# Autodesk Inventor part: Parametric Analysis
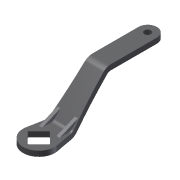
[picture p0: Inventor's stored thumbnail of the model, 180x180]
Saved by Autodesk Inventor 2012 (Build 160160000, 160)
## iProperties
Created: 2008-02
Part Number: Parametric Analysis
Material: Domex 355_SM
Document SubType Name: Sheet Metal
Designer: maxfiep
Density: 7.8 g/cm^3
Mass: 6351 g
Surface Area: 1123.64 cm^2
Volume: 814.231 cm^3
Sheet Metal Rule: Default
RuleStatus: InUse
Author: maxfiep
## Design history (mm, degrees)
node "Contour Flange1"
  sketch "Sketch1"
    geometry: L1 (0, 0)-(80, 0); L2 (80, 0)-(220, 140); L3 (220, 140)-(411, 140); L4 (0, 168)-(0, -28) reference; L5 (-82.2, 0)-(493.2, 0) reference; 1 further point
    constraints: 6 end point, 1 parallel
    dimensions: "d0" = 140 distance between parallel lines of L3 L1; "d2" = 135 deg angle of L3 L2; "d3" = 80 distance of L1.start L1.end
node "Face1"
  sketch "Sketch2"
    geometry: L1 (0, 71.716)-(0, 0) reference; L2 (120, 71.716)-(0, 71.716) reference; L3 (0, 71.716)-(0, 0) reference; L4 (120, 0)-(0, 0) reference; L5 (120, 71.716)-(120, 0) reference; A1 r 60 centre (60, 0) between (0, 0) and (120, 0); 1 further point
    constraints: 2 point on circle, 2 tangent, 1 centre point
sketch "Sketch3"
  geometry: L1 (0, 0)-(0, -71.716) reference; L2 (120, 0)-(120, -71.716) reference; L3 (0, -71.716)-(120, -71.716); L4 (60, -71.716)-(60, 0); L5 (17.574, -71.716)-(60, -29.289); L6 (60, -29.289)-(102.426, -71.716); L7 (102.426, -71.716)-(60, -114.142); L8 (60, -114.142)-(17.574, -71.716); 2 further points
  constraints: 12 end point, 2 coincident, 2 perpendicular, 1 horizontal alignment, 1 midpoint, 1 point on line, 11 other
  dimensions: "d19" = 60 distance of L7.end L5.start
cut "Cut1" sketch "Sketch3" dims "d22" = 20 (= Thickness), "d23" = 0
sketch "Sketch4"
  geometry: L1 (0, 0)-(120, 0) reference; L2 (-1489.511, -411)-(1609.511, -411) reference; L3 (0, -174.431)-(120, -174.431) reference; L4 (25, -174.431)-(25, 0); L5 (0, -174.431)-(0, 0) reference; L6 (60, -174.431)-(60, -411); L7 (60, -471)-(60, -923.049); L8 (25, 0)-(-30.859, 0); L9 (-30.859, 0)-(-30.859, -503.072); L10 (-30.859, -503.072)-(60, -503.072); L11 (150.859, -503.072)-(60, -503.072); L12 (150.859, 0)-(150.859, -503.072); L13 (95, -174.431)-(95, 0); L14 (95, 0)-(150.859, 0); A1 r 60 centre (60, -411) between (0, -411) and (120, -411) reference; A2 r 60 centre (60, -411) between (1.325, -398.459) and (60, -471); A3 r 1071.794 centre (-1046.794, -174.431) between (1.325, -398.459) and (25, -174.431); A4 r 60 centre (60, -411) between (60, -471) and (118.675, -398.459); A5 r 1071.794 centre (1166.794, -174.431) between (95, -174.431) and (118.675, -398.459)
  constraints: 20 end point, 9 point on circle, 6 symmetric about line, 4 centre point, 4 perpendicular, 3 point on line, 2 coincident, 2 midpoint, 2 tangent, 1 concentric, 1 horizontal, 1 parallel, 2 other
  dimensions: "d24" = 25 distance between parallel lines of L4 L5
cut "Cut2" sketch "Sketch4" dims "d25" = 20 (= Thickness), "d26" = 0
sketch "Sketch5"
  geometry: L1 (70, -174.431)-(70, 0) reference; L2 (0, 0)-(70, 0) reference; L3 (0, 0)-(0, -174.431) reference; L4 (0, -174.431)-(70, -174.431) reference; A1 r 35 centre (35, 0) between (70, 0) and (0, 0); 1 further point
  constraints: 2 point on circle, 2 tangent, 1 centre point, 1 coincident
  node "Projected Loop2"
node "Face2"
hole "Hole1" sketch "Sketch5" diameter "d32" = 25; stored, may be unused: countersink angle "d36" = 90 deg, drill point angle "d38" = 118 deg; dims "d33" = 6, "d34" = 4, "d35" = 2, "d37" = 20 (= Thickness)
fillet "Fillet1" dims "d39" = 1
feature "Corner Round1" dims "d40" = 3
workplane "Work Plane1"
workplane "Work Plane2"
sketch "Sketch7"
  geometry: L1 (92.998, 108)-(92.998, 48); L2 (27.002, 108)-(27.002, 48); L3 (27.002, 78)-(92.998, 78); 6 further points; 1 other entity
  constraints: 6 end point, 3 midpoint, 2 vertical, 1 horizontal, 1 parallel, 1 vertical alignment, 4 other
  dimensions: "d77" = 78 distance of point (60, 0) point (60, 78); "d78" = 60 distance of L1.start L1.end
feature "Rib1" sketch "Sketch7" dims "d79" = 12, "d80" = 1, "d81" = 0
body "Solid1"
face "Plate1" dims "d4" = 20 (= BendReliefWidth), "d5" = 10 (= BendReliefDepth), "d6" = 40 (= MinimumRemnant), "d7" = 20 (= BendRadius), "d8" = 120, "d9" = 20 (= BendRadius), "d10" = 0.5, "d11" = 80 (= CornerReliefSize), "d12" = 20 (= Thickness), "d13" = 20 (= JacobiRadiusSize), "SeamGap" = 0.01, "Thickness" = 20 (derived)
bend "Bend1" dims "d4" = 20 (= BendReliefWidth), "d5" = 10 (= BendReliefDepth), "d6" = 40 (= MinimumRemnant), "d7" = 20 (= BendRadius), "d9" = 20 (= BendRadius), "d10" = 0.5, "SeamGap" = 0.01, "Thickness" = 20 (derived)
feature "Corner1" dims "d10" = 0.5, "d11" = 80 (= CornerReliefSize), "d12" = 20 (= Thickness), "d13" = 20 (= JacobiRadiusSize)
node "Projected Loop1"
face "Plate2" dims "d14" = 20 (= BendRadius), "d15" = 20 (= BendReliefWidth), "d17" = 40 (= MinimumRemnant), "Thickness" = 20 (derived)
bend "Bend2" dims "d14" = 20 (= BendRadius), "d15" = 20 (= BendReliefWidth), "d16" = 10 (= BendReliefDepth), "d17" = 40 (= MinimumRemnant), "d18" = 20 (= BendRadius), "SeamGap" = 0.01, "Thickness" = 20 (derived)
face "Plate3" dims "d27" = 20 (= BendRadius), "d28" = 20 (= BendReliefWidth), "d30" = 40 (= MinimumRemnant), "Thickness" = 20 (derived)
bend "Bend3" dims "d27" = 20 (= BendRadius), "d28" = 20 (= BendReliefWidth), "d29" = 10 (= BendReliefDepth), "d30" = 40 (= MinimumRemnant), "d31" = 20 (= BendRadius), "SeamGap" = 0.01, "Thickness" = 20 (derived)
other parameters: "BendRadius" = 20 (= Thickness), "d71" = 0, "d72" = 0, "d73" = 22.5 deg, "d76" = -15
